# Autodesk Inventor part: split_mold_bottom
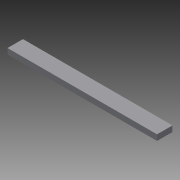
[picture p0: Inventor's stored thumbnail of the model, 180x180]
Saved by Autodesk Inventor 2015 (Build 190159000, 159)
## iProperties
Created: 2015-04
Part Number: split_mold_bottom
Material: Generic
Document SubType Name: Modeling
Designer: sungeun
Density: 1 g/cm^3
Appearance: Default
Author: sungeun
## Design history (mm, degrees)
sketch "Sketch18"
  geometry: L1 (90, -7.5)-(-90, -7.5); L2 (-90, -7.5)-(-90, 7.5); L3 (-90, 7.5)-(90, 7.5); L4 (90, 7.5)-(90, -7.5); L5 (90, -7.5)-(-90, 7.5); L6 (-90, -7.5)-(90, 7.5); L7 (92, 9.5)-(-92, 9.5); L8 (-92, 9.5)-(-92, -9.5); L9 (-92, -9.5)-(92, -9.5); L10 (92, -9.5)-(92, 9.5); 1 further point
  constraints: 20 end point, 4 parallel, 2 midpoint, 2 perpendicular, 1 horizontal, 3 other
  dimensions: "d56" = 180 distance of L2.end L3.end; "d57" = 15 distance of L1.end L2.end; "d58" = 2 distance between parallel lines of L3 L7
extrude "Extrusion13" new body sketch "Sketch18" distance "d59" = 3; taper "d60" = 0 deg
sketch "Sketch19"
  geometry: L1 (-90, -7.5)-(90, -7.5) reference; L2 (90, -7.5)-(90, 7.5) reference; L3 (90, 7.5)-(-90, 7.5) reference; L4 (-90, 7.5)-(-90, -7.5) reference; L5 (-92, 9.5)-(92, 9.5); L6 (92, 9.5)-(92, -9.5); L7 (92, -9.5)-(-92, -9.5); L8 (-92, -9.5)-(-92, 9.5); 1 further point
  constraints: 8 end point, 3 other
  dimensions: "d61" = 2 distance between parallel lines of L3 L5
extrude "Extrusion14" join sketch "Sketch19" distance "d62" = 7; taper "d63" = 0 deg
body "Solid5"
node "Projected Loop4"
